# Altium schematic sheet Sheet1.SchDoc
size A4
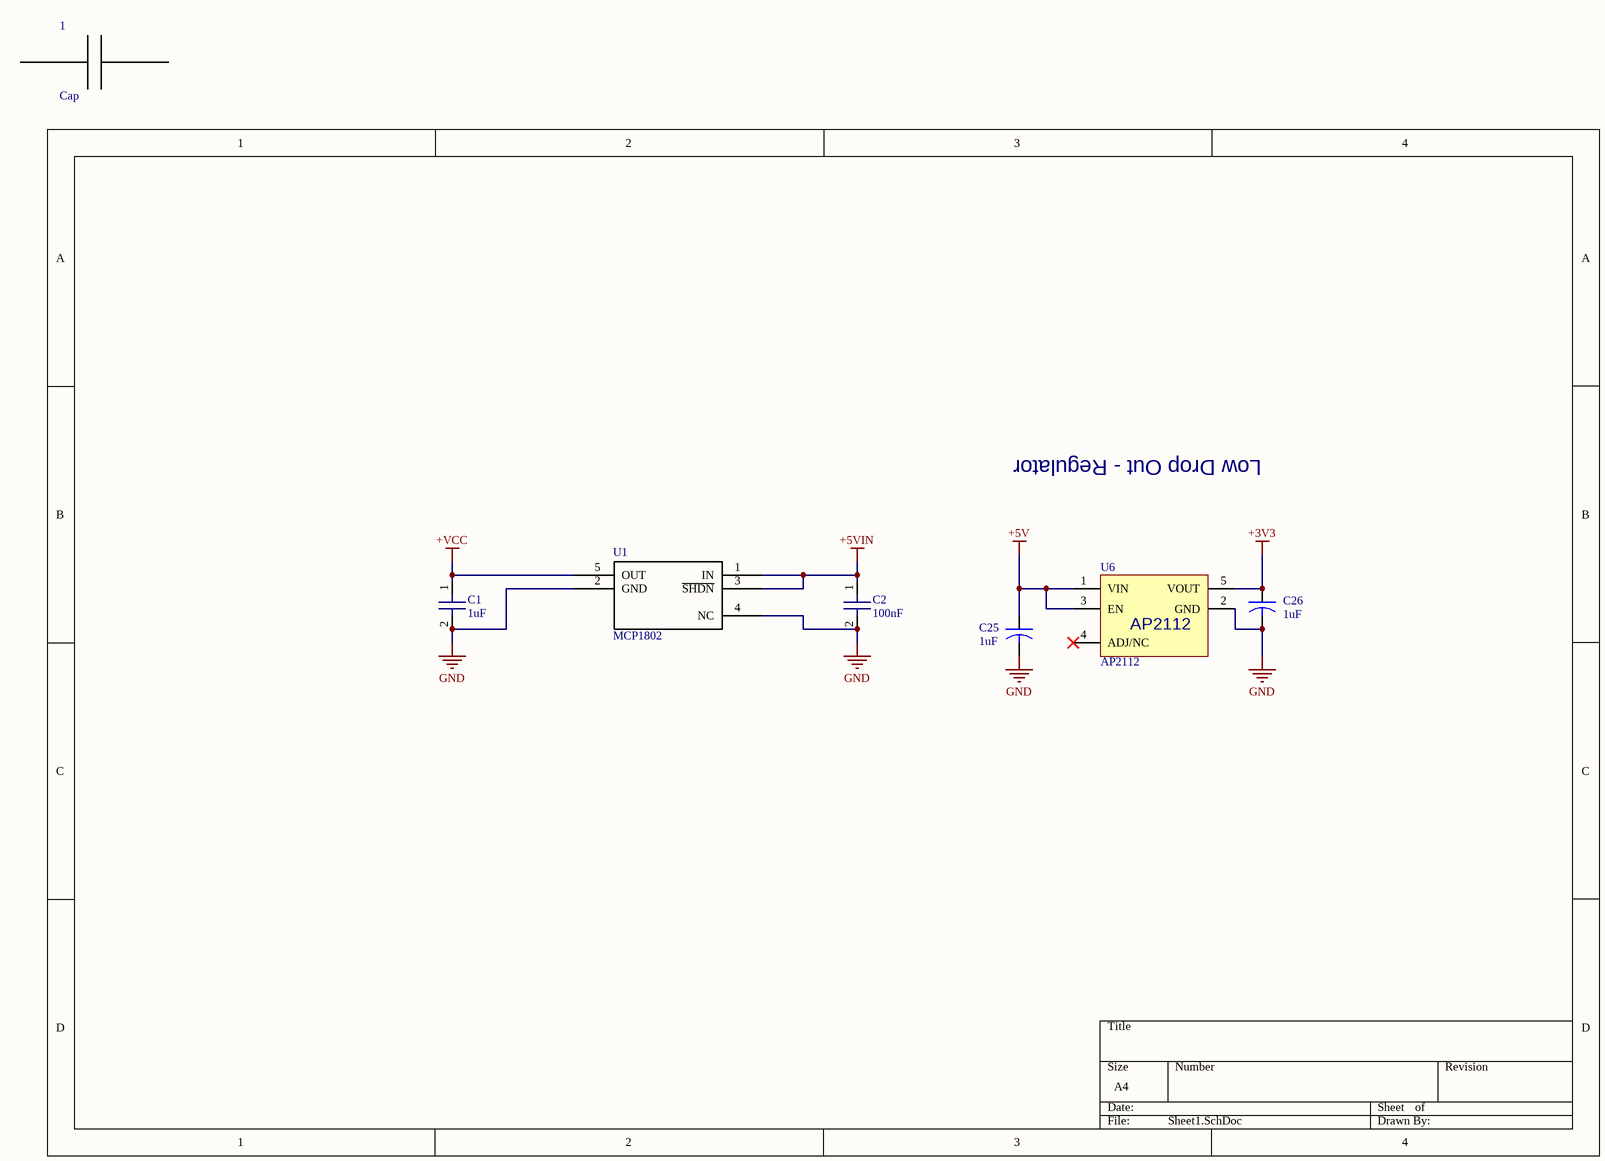
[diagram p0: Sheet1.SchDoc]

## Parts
1  Cap
C1  1uF  [CAPC1005X06N]
C2  100nF  [CAPC1005X06N]
C25  1uF  [CC1608-0603]
C26  1uF  [CC1608-0603]
U1  MCP1802  [MCP1802_SOT23-5]
U6  AP2112  [SOT95P280X145-5N]

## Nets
+3V3: C26.1 U6.5(VOUT)
+5V: C25.1 U6.1(VIN) U6.3(EN)
+5VIN: C2.1 U1.1(IN) U1.3(~{SHDN})
+VCC: C1.1 U1.5(OUT)
GND: C1.2 C2.2 C25.2 C26.2 U1.2(GND) U1.4(NC) U6.2(GND)

Not connected (* = marked no-connect by the designer): 1 ?1 ?2; U6 4(ADJ/NC)*

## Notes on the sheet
- Low Drop Out - Regulator

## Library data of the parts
C1 C2 = Cap
C25 C26 = CAPACITOR: Current Rating: A; Voltage Rated: 16V
U1 = MCP1802: 300 mA, High PSRR, Low Quiescent Current LDO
